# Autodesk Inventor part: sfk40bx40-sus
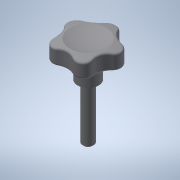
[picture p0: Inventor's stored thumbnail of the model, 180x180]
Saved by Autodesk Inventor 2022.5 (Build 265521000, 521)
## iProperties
Created: 2016-12
Part Number: sfk40bx40-sus
Material: 一般
Document SubType Name: Modeling
Designer: imaocorp
Density: 1 g/cm^3
Appearance: 既定
Author: imaocorp
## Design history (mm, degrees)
node "sfk40bx40-sus.x_t1"
node "sfk40bx40-sus"
node "Base1"
